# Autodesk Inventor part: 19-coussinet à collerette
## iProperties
Created: 2011-02
Part Number: 19-coussinet à collerette
Document SubType Name: Modeling
Designer: eric
Density: 1 g/cm^3
Author: eric
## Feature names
1. Base1
